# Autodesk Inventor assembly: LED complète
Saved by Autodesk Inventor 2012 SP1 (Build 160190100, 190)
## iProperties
Created: 2014-12
Part Number: LED complète
Document SubType Name: Assembly
Designer: Bruno
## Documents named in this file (3)
- D:\Cours\Systèmes\secateur-hydrogene-Pragma\Documentation\Dossier technique Infaco F3005\Solidworks\Composants importés\F3005\LED complète.iam
- D:\Cours\Systèmes\secateur-hydrogene-Pragma\Documentation\Dossier technique Infaco F3005\Solidworks\Composants importés\F3005\Cache LED.ipt
- D:\Cours\Systèmes\secateur-hydrogene-Pragma\Documentation\Dossier technique Infaco F3005\Solidworks\Composants importés\F3005\Led.ipt
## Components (2 placed, 2 different names)
1. Cache LED:1
2. Led:1
